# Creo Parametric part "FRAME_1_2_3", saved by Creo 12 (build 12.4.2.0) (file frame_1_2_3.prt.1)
Units: Custom; MM, KILOGRAM, SECS

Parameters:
  PTC_WM_ITERATION = "0"
  PTC_WM_VERSION = "-.0"
  PTC_WM_LIFECYCLE_STATE = "In Work"
  PTC_WM_LIFECYCLE = "MO_CADDocument"
  PTC_WM_CREATED_BY = "Maximilian Roepper (Z0017RMS: MO)"
  PTC_WM_CREATED_ON = "18-Sep-26 11:36:42 AM"
  PTC_WM_MODIFIED_BY = "Maximilian Roepper (Z0017RMS: MO)"
  PTC_WM_MODIFIED_ON = "18-Sep-26 11:36:46 AM"
  PDMLINKNUMBER = "PDM000071455038"
  PTC_WM_NAME = "frame_1_2_3.prt"
  PTC_WM_NUMBER = "PDM000071455038"

Other parameters: WEIGHT, WEIGHT_FACTOR, WEIGHT_ADD, _MASS_TEMP, _DIFF_TEMP, MC_ERRORS, SUPPLIER

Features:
  1. coordinate system
  2. datum plane "PRT_YZ"
  3. datum plane "PRT_XY"
  4. datum plane "PRT_XZ"
  5. coordinate system
  6. datum axis
  7. datum axis
  8. datum axis
  9. coordinate system
  10. imported feature
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
Other named items: PRT, SIEMENS_MO, DRW_VIEW_ORG, PRT_X, PRT_Y, PRT_Z, CS0, ROUGH_GROB

Layers: 00_STD_CSYS-KSYS, 01_STD_PLANES-EBENEN, 02_STD_AXES-ACHSEN, 03_STD_CSYS-KSYS, 24_IMPORT_FEAT-IMPORT_KE

Surfaces: 62 plane, 8 cylinder, 8 torus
